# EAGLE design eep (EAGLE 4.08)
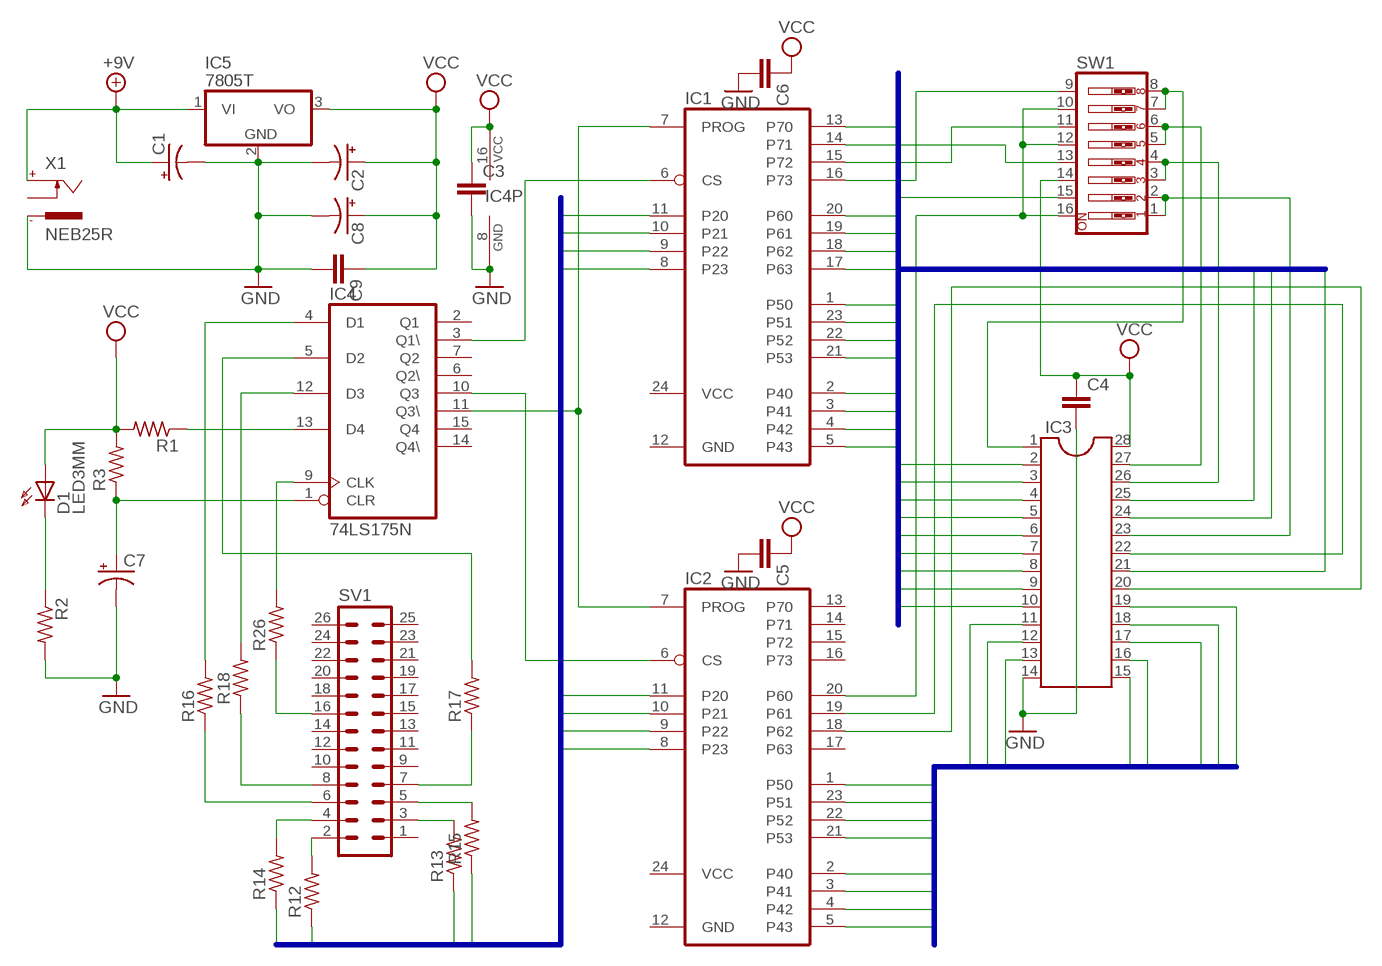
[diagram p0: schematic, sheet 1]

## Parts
C1  CPOL-USTAP5-80  [TAP5-80]
C2  CPOL-USTT2D5  [TT2D5]
C3  C5/2.5  [C5B2.5]
C4  C5/2.5  [C5B2.5]
C5  C5/2.5  [C5B2.5]
C6  C5/2.5  [C5B2.5]
C7  CPOL-USTAP5-50  [TAP5-50]
C8  CPOL-USTAP5-45  [TAP5-45]
C9  C5/2.5  [C5B2.5]
D1  LED3MM  [LED3MM]
IC1  IOEX-8243  [DIL24-6]
IC2  IOEX-8243  [DIL24-6]
IC3  DIL28  [DIL28-6]
IC4  74LS175N  [DIL16]
IC5  7805T  [TO220H]
R1  R-US_0207/10  [0207/10]
R2  R-US_0207/10  [0207/10]
R3  R-US_0207/10  [0207/10]
R12  R-US_0207/10  [0207/10]
R13  R-US_0207/10  [0207/10]
R14  R-US_0207/10  [0207/10]
R15  R-US_0207/10  [0207/10]
R16  R-US_0207/10  [0207/10]
R17  R-US_0207/10  [0207/10]
R18  R-US_0207/10  [0207/10]
R26  R-US_0207/10  [0207/10]
SV1  MA13-2  [MA13-2]
SW1  SW_DIP-8  [EDG-08]
X1  NEB25R  [NEB25R]

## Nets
+9V: C1.+ IC5.1(VI) X1.+
A11WE: IC3.23 SW1.1 SW1.2
A13VCC: IC3.26 SW1.3 SW1.4
A14WE: IC3.27 SW1.5 SW1.6
A15WE: IC3.1 SW1.7 SW1.8
AB0: IC1.2(P40) IC3.10
AB1: IC1.3(P41) IC3.9
AB2: IC1.4(P42) IC3.8
AB3: IC1.5(P43) IC3.7
AB4: IC1.1(P50) IC3.6
AB5: IC1.23(P51) IC3.5
AB6: IC1.22(P52) IC3.4
AB7: IC1.21(P53) IC3.3
AB8: IC1.20(P60) IC3.25
AB9: IC1.19(P61) IC3.24
AB10: IC1.18(P62) IC3.21
AB11: IC1.17(P63) SW1.15
AB12: IC1.13(P70) IC3.2
AB13: IC1.14(P71) SW1.13
AB14: IC1.15(P72) SW1.11
AB15: IC1.16(P73) SW1.9
CE: IC2.18(P62) IC3.20
CLK: IC4.9(CLK) R26.2
CLR: C7.+ IC4.1(CLR) R3.1
CS1: IC1.6(CS) IC4.3(Q1\)
CS2: IC2.6(CS) IC4.10(Q3)
D1: IC4.4(D1) R16.2
D2: IC4.5(D2) R17.2
D3: IC4.12(D3) R18.2
D4: IC4.13(D4) R1.1
DB0: IC2.2(P40) IC3.11
DB1: IC2.3(P41) IC3.12
DB2: IC2.4(P42) IC3.13
DB3: IC2.5(P43) IC3.15
DB4: IC2.1(P50) IC3.16
DB5: IC2.23(P51) IC3.17
DB6: IC2.22(P52) IC3.18
DB7: IC2.21(P53) IC3.19
GND [power]: C1.- C2.- C3.2 C4.2 C5.2 C6.2 C7.- C8.- C9.2 IC3.14 IC4.8(GND) IC5.2(GND) R2.2 X1.-
N$20: D1.K(C) R2.1
NC2: R12.2 SV1.2
NC3: R13.2 SV1.3
NC4: R14.2 SV1.4
NC5: R15.2 SV1.5
NC6: R16.1 SV1.6
NC7: R17.1 SV1.7
NC8: R18.1 SV1.8
NC16: R26.1 SV1.16
OE: IC2.19(P61) IC3.22
PROG: IC1.7(PROG) IC2.7(PROG) IC4.11(Q3\)
PROG0: IC1.11(P20) IC2.11(P20) R12.1
PROG1: IC1.10(P21) IC2.10(P21) R13.1
PROG2: IC1.9(P22) IC2.9(P22) R14.1
PROG3: IC1.8(P23) IC2.8(P23) R15.1
VCC [power]: C2.+ C3.1 C4.1 C5.1 C6.1 C8.+ C9.1 D1.A IC3.28 IC4.16(VCC) IC5.3(VO) R1.2 R3.2 SW1.14
WE: IC2.20(P60) SW1.10 SW1.12 SW1.16
Unconnected: IC2.13(P70) IC2.14(P71) IC2.15(P72) IC2.16(P73) IC2.17(P63) IC4.2(Q1) IC4.6(Q2\) IC4.7(Q2) IC4.14(Q4\) IC4.15(Q4) SV1.1 SV1.9 SV1.10 SV1.11 SV1.12 SV1.13 SV1.14 SV1.15 SV1.17 SV1.18 SV1.19 SV1.20 SV1.21 SV1.22 SV1.23 SV1.24 SV1.25 SV1.26 X1.C

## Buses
PROG[0..3]
DB[0..7]
AB[0..15]

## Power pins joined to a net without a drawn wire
GND: IC1.12(GND) IC2.12(GND)
VCC: IC1.24(VCC) IC2.24(VCC)

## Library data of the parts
C1 C2 C7 C8 = rcl:CPOL-US: POLARIZED CAPACITOR, American symbol
C3-C6 C9 = capacitor-wima:C: CAPACITOR
D1 = led:LED3MM: LED
IC1 IC2 = micro-intel:IOEX-8243: MICROCOMPUTER/PERIPHERAL DEVICE
IC3 = dil:DIL28: SOCKET Dual In Line
IC4 = 74xx-us:74*175: Qadruple D type FLIP FLOP, clear
IC5 = linear:78*: Positive VOLTAGE REGULATOR
R1-R3 R12-R18 R26 = rcl:R-US_: RESISTOR, American symbol
SV1 = con-lstb:MA13-2: PIN HEADER
SW1 = special:SW_DIP-8: DIP SWITCH
X1 = con-lumberg:NEB25R: CONNECTOR

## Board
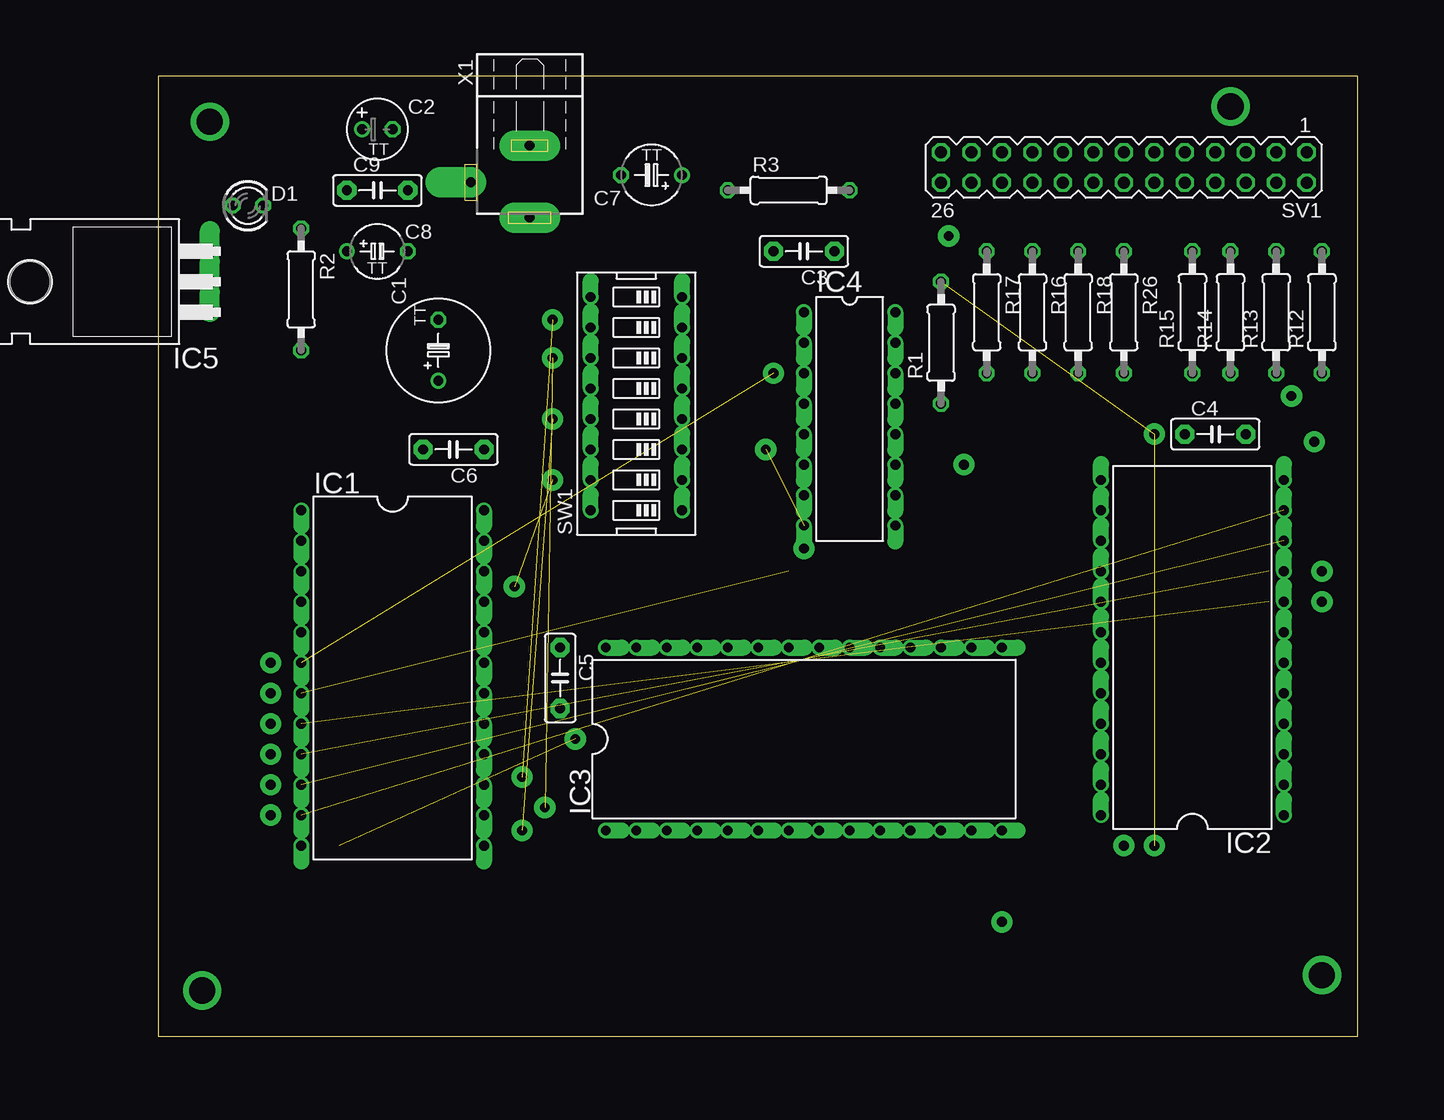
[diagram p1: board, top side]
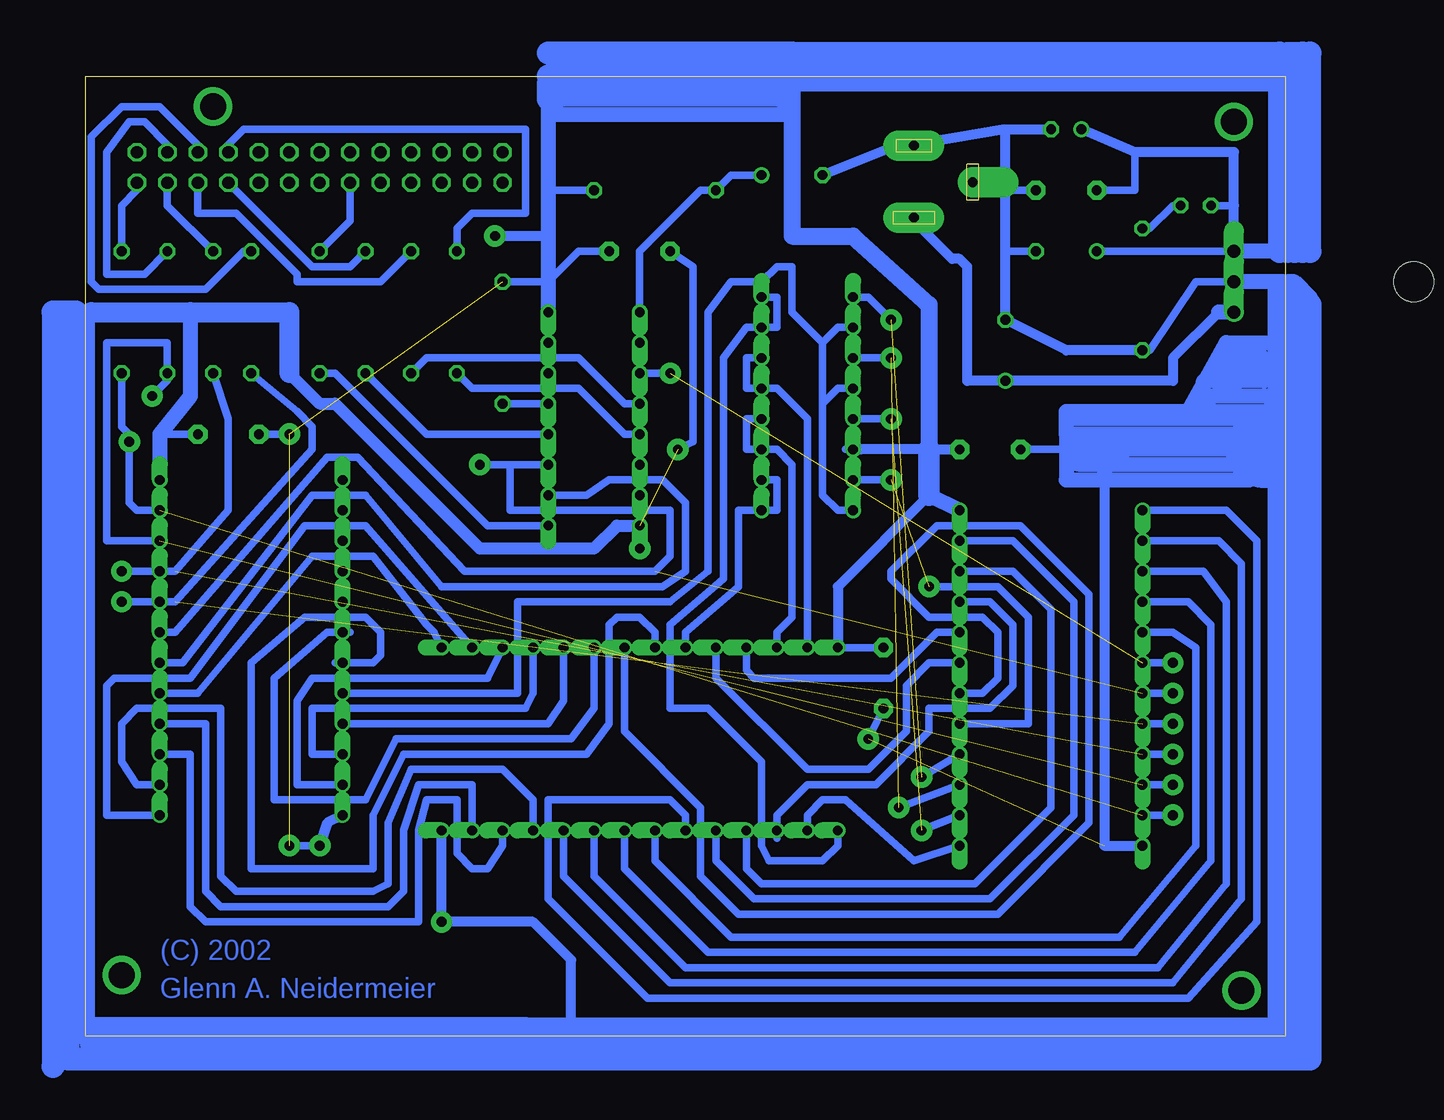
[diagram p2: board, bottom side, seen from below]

Size 100 x 80 mm. Coordinates in mm from the lower left corner, seen from the top.
Outline: 0,0 100,0 100,80 0,80 0,0
Copper layers used: Bottom

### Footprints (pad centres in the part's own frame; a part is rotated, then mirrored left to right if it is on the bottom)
TAP5-80 = drill 0.813 round: + -2.54,0 | drill 0.813 octagon: - 2.54,0
TT2D5 = drill 0.813 round: + -1.27,0 | drill 0.813 octagon: - 1.27,0
C5B2.5 = drill 0.813 pad 1.6 octagon: 1 -2.54,0; 2 2.54,0
TAP5-50 = drill 0.813 round: + -2.54,0 | drill 0.813 octagon: - 2.54,0
TAP5-45 = drill 0.813 round: + -2.54,0 | drill 0.813 octagon: - 2.54,0
LED3MM = drill 0.813 octagon: A -1.27,0; K 1.27,0
DIL24-6 = drill 0.813 offset: 1 -13.97,-7.62; 2 -11.43,-7.62; 3 -8.89,-7.62; 4 -6.35,-7.62; 5 -3.81,-7.62; 6 -1.27,-7.62; 7 1.27,-7.62; 8 3.81,-7.62; 9 6.35,-7.62; 10 8.89,-7.62; 11 11.43,-7.62; 12 13.97,-7.62; 13 13.97,7.62; 14 11.43,7.62; 15 8.89,7.62; 16 6.35,7.62; 17 3.81,7.62; 18 1.27,7.62; 19 -1.27,7.62; 20 -3.81,7.62; 21 -6.35,7.62; 22 -8.89,7.62; 23 -11.43,7.62; 24 -13.97,7.62
DIL28-6 = drill 0.813 offset: 1 -16.51,-7.62; 2 -13.97,-7.62; 3 -11.43,-7.62; 4 -8.89,-7.62; 5 -6.35,-7.62; 6 -3.81,-7.62; 7 -1.27,-7.62; 8 1.27,-7.62; 9 3.81,-7.62; 10 6.35,-7.62; 11 8.89,-7.62; 12 11.43,-7.62; 13 13.97,-7.62; 14 16.51,-7.62; 15 16.51,7.62; 16 13.97,7.62; 17 11.43,7.62; 18 8.89,7.62; 19 6.35,7.62; 20 3.81,7.62; 21 1.27,7.62; 22 -1.27,7.62; 23 -3.81,7.62; 24 -6.35,7.62; 25 -8.89,7.62; 26 -11.43,7.62; 27 -13.97,7.62; 28 -16.51,7.62
DIL16 = drill 0.813 offset: 1 -8.89,-3.81; 2 -6.35,-3.81; 3 -3.81,-3.81; 4 -1.27,-3.81; 5 1.27,-3.81; 6 3.81,-3.81; 7 6.35,-3.81; 8 8.89,-3.81; 9 8.89,3.81; 10 6.35,3.81; 11 3.81,3.81; 12 1.27,3.81; 13 -1.27,3.81; 14 -3.81,3.81; 15 -6.35,3.81; 16 -8.89,3.81
TO220H = drill 1.118 offset: 1 -2.54,-10.16; 2 0,-10.16; 3 2.54,-10.16 | hole 3.302: 0,4.826
0207/10 = drill 0.813 octagon: 1 -5.08,0; 2 5.08,0
MA13-2 = drill 1.016 octagon: 1 -15.24,-1.27; 2 -15.24,1.27; 3 -12.7,-1.27; 4 -12.7,1.27; 5 -10.16,-1.27; 6 -10.16,1.27; 7 -7.62,-1.27; 8 -7.62,1.27; 9 -5.08,-1.27; 10 -5.08,1.27; 11 -2.54,-1.27; 12 -2.54,1.27; 13 0,-1.27; 14 0,1.27; 15 2.54,-1.27; 16 2.54,1.27; 17 5.08,-1.27; 18 5.08,1.27; 19 7.62,-1.27; 20 7.62,1.27; 21 10.16,-1.27; 22 10.16,1.27; 23 12.7,-1.27; 24 12.7,1.27; 25 15.24,-1.27; 26 15.24,1.27
EDG-08 = drill 0.813 offset: 1 -8.89,-3.81; 2 -6.35,-3.81; 3 -3.81,-3.81; 4 -1.27,-3.81; 5 1.27,-3.81; 6 3.81,-3.81; 7 6.35,-3.81; 8 8.89,-3.81; 9 8.89,3.81; 10 6.35,3.81; 11 3.81,3.81; 12 1.27,3.81; 13 -1.27,3.81; 14 -3.81,3.81; 15 -6.35,3.81; 16 -8.89,3.81
NEB25R = drill 0.813 pad 2.54 long: + 0,7.35; - 0,1.35 | drill 0.813 pad 2.54 offset: C 4.9,4.4

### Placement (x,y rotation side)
C1  23.33,57.15 90 top
C2  18.25,75.56 0 top
C3  53.81,65.4 180 top
C4  88.1,50.16 0 top
C5  33.49,29.84 270 top
C6  24.6,48.89 180 top
C7  41.11,71.75 180 top
C8  18.25,65.4 0 top
C9  18.25,70.48 0 top
D1  7.46,69.21 0 top
IC1  19.52,29.84 270 top
IC2  86.19,32.38 90 top
IC3  53.81,24.76 0 top
IC4  57.62,51.43 270 top
IC5  -5.88,62.86 90 top
R1  65.24,57.78 90 top
R2  11.9,62.23 270 top
R3  52.54,70.48 0 top
R12  96.99,60.32 90 top
R13  93.18,60.32 90 top
R14  89.37,60.32 90 top
R15  86.19,60.32 90 top
R16  72.86,60.32 270 top
R17  69.05,60.32 270 top
R18  76.67,60.32 270 top
R26  80.48,60.32 270 top
SV1  80.48,72.38 180 top
SW1  39.84,52.7 90 top
X1  30.95,75.56 180 top

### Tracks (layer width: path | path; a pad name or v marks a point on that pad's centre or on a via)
+9V
  Bottom 0.61: 30.95,67.94 X1.+
  Bottom 0.813: 30.95,67.94 27.77,64.77 27.14,64.77 26.5,64.13 26.5,54.61 C1.+ 9.36,54.61 9.36,56.51 5.55,60.32
  Bottom 1.27: IC5.1 5.55,60.32
A11WE
  Bottom 0.61: SW1.2 42.38,46.35 42.38,43.81 SW1.1 45.55,43.81 45.55,37.46 50,33.65 IC3.23
A13VCC
  Bottom 0.61: IC3.26 42.38,33.65 41.11,34.92 41.11,47.62 42.38,48.89 SW1.3 44.92,48.89 44.92,51.43 SW1.4
A14WE
  Bottom 0.61: IC3.27 39.84,51.43 42.38,53.97 SW1.5 44.92,53.97 44.92,56.51 SW1.6
A15WE
  Bottom 0.61: SW1.8 42.38,61.59 42.38,59.05 SW1.7 44.92,59.05 46.82,56.51 46.82,38.1 47.5,37.51 51.27,34.29 51.27,27.3 48.09,27.3 43.65,22.86 43.65,15.87 43.02,14.6 38.57,14.6 37.3,15.87 IC3.1
AB0
  Bottom 0.61: IC1.2 5.55,41.27 3.64,39.37 3.64,11.43 9.36,4.44 51.27,4.44 60.16,13.33 IC3.10
AB1
  Bottom 0.61: IC1.3 6.82,38.73 4.92,36.19 4.92,12.7 10.63,5.71 50,5.71 57.62,13.33 IC3.9
AB2
  Bottom 0.61: IC3.8 55.08,13.97 48.09,6.98 12.54,6.98 6.18,14.6 6.18,34.29 8.09,36.19 IC1.4
AB3
  Bottom 0.61: IC3.7 52.54,14.6 46.19,8.25 13.81,8.25 7.46,15.87 7.46,32.38 9.36,33.65 IC1.5
AB4
  Bottom 0.61: IC1.1 4.92,43.81 2.38,41.27 2.38,9.52 8.09,3.17 53.17,3.17 61.43,11.43 61.43,19.68 51.27,19.68 50,18.41 IC3.6
AB5
  Bottom 0.61: IC3.5 47.46,14.6 44.28,11.43 24.6,11.43 17.61,18.41 17.61,36.19 22.7,41.27 IC1.23
AB6
  Bottom 0.61: IC3.4 44.92,13.97 43.65,12.7 25.87,12.7 19.52,19.04 19.52,35.55 22.7,38.73 IC1.22
AB7
  Bottom 0.61: IC1.21 24.6,36.19 22.7,34.29 22.7,29.2 24.6,27.3 29.68,27.3 29.68,25.39 34.12,20.95 39.84,20.95 42.38,18.41 IC3.3 42.38,16.5
AB8
  Bottom 0.61: IC3.25 44.92,30.47 44.28,29.84 32.85,29.84 29.04,33.65 IC1.20
AB9
  Bottom 0.61: IC1.19 29.68,31.11 31.58,29.2 31.58,25.39 34.76,22.22 39.84,22.22 47.46,29.84 IC3.24
AB10
  Bottom 0.61: IC3.21 55.08,25.39 48.73,19.04 48.73,13.33 45.55,10.16 23.96,10.16 16.34,17.77 16.34,36.83 22.06,42.54 29.04,42.54 32.85,38.73 32.85,38.1 29.68,34.92 25.23,34.92 23.96,33.65 23.96,29.84 25.23,28.57 IC1.18
AB11  (via drill 0.81 pad 1.78)  (1 unrouted)
  Bottom 0.61: IC1.17 21.42,26.03 21.42,34.92 23.96,37.46 v29.68,37.46 | v32.85,46.35 SW1.15
AB12
  Bottom 0.61: IC1.13 30.95,14.6 36.66,19.68 38.57,19.68 39.84,18.41 IC3.2
AB13  (via drill 0.81 pad 1.78)  (1 unrouted)
  Bottom 0.61: IC1.14 v30.31,17.14 | v32.85,51.43 SW1.13
AB14  (via drill 0.81 pad 1.78)  (1 unrouted)
  Bottom 0.61: IC1.15 v32.22,19.04 | v32.85,56.51 SW1.11
AB15  (via drill 0.81 pad 1.78)  (1 unrouted)
  Bottom 0.61: IC1.16 v30.31,21.58 | SW1.9 34.76,61.59 v32.85,59.69
CE
  Bottom 0.61: IC3.20 57.62,27.3 59.52,24.76 74.13,24.76 76.67,19.68 84.29,19.68 84.29,29.84 79.84,33.65 IC2.18 77.94,33.65
CLK
  Bottom 0.61: IC4.9 66.51,42.54 79.21,55.24 R26.2
CLR
  Bottom 0.61: IC4.1 53.81,65.4 48.73,70.48 R3.1 46.19,71.75 C7.+
CS1  (via drill 0.81 pad 1.78)  (1 unrouted)
  Bottom 0.61: v9.36,31.11 IC1.6 | v51.27,55.24 IC4.3
CS2
  Bottom 0.61: IC4.10 58.25,45.08 56.35,46.35 51.91,46.35 50,44.45 50,38.73 51.91,37.46 70.32,37.46 76.67,45.08 81.11,45.08 91.91,31.11 IC2.6
D1
  Bottom 0.61: R16.2 71.59,56.51 58.89,56.51 55.08,52.7 IC4.4
D2
  Bottom 0.61: R17.2 67.78,53.97 58.89,53.97 55.08,50.16 IC4.5
D3
  Bottom 0.61: R18.2 71.59,50.16 IC4.12
D4
  Bottom 0.61: IC4.13 R1.1
DB0
  Bottom 0.61: IC3.11 62.7,19.68 65.24,22.22 72.86,22.22 74.77,17.77 74.77,12.7 76.03,12.06 87.47,12.06 88.73,13.33 88.73,27.3 95.72,27.3 96.99,26.03 96.99,22.86 95.72,20.95 IC2.2
DB1
  Bottom 0.61: IC2.3 91.28,23.49 91.28,10.79 90,9.52 72.22,9.52 72.22,17.14 71.59,19.68 69.05,19.68 69.05,15.24 67.78,13.97 66.51,13.97 65.24,15.87 IC3.12
DB2
  Bottom 0.61: IC3.13 67.78,20.95 72.22,20.95 73.5,17.14 73.5,12.06 74.77,10.79 88.73,10.79 90,12.06 90,26.03 IC2.4
DB3
  Bottom 0.61: IC3.15 70.95,33.65 71.59,34.29 76.03,40 81.11,40 90.64,28.57 IC2.5
DB4
  Bottom 0.61: IC3.16 76.67,42.54 81.75,42.54 91.28,29.84 97.62,29.84 98.26,29.2 98.26,18.41 IC2.1
DB5
  Bottom 0.61: IC3.17 66.51,29.84 81.11,29.84 82.39,27.93 82.39,20.95 IC2.23
DB6
  Bottom 0.61: IC3.18 62.7,28.57 63.34,27.3 81.11,27.3 81.11,23.49 IC2.22
DB7
  Bottom 0.61: IC3.19 60.16,27.93 61.43,26.03 IC2.21
GND  (via drill 0.81 pad 1.78)  (2 unrouted)
  Bottom 0.61: 16.98,48.89 C6.2 | v34.76,24.76 C5.2 | 99.53,0.63 99.53,60.32 | R2.2 11.27,57.15 7.46,62.86 IC5.2 | 23.33,70.48 C9.2 | 23.33,65.4 C8.- | 29.71,74.5 29.68,74.29 X1.- 32.22,74.29 | IC4.8 v53.81,40.64 | 93.81,50.16 C4.2 | v50.63,48.89 49.37,49.53 49.37,64.13 C3.2
  Bottom 0.813: IC3.14 v70.32,9.52 62.7,9.52 59.52,6.34 59.52,1.27 60.16,0.63 63.34,0.63 | 15.08,47.62 15.08,48.89 | 15.08,46.35 15.08,15.87 IC1.12 | IC4.8 55.08,42.54 | R2.2 18.25,57.15 C1.- 23.33,65.4 23.33,70.48 23.33,75.56 | 23.33,75.56 C2.- | 23.33,75.56 29.71,74.5 30.95,74.29 | 32.22,74.29 C7.-
  Bottom 1.016: 83.02,55.24 80.48,52.7 79.21,52.7 67.14,40.64 57.62,40.64 55.71,42.54 IC4.8
  Bottom 1.27: 1.74,48.89 2.38,48.89 | 2.38,48.89 2.38,50.16 | 2.38,50.16 13.17,50.16 13.17,48.89 3.64,48.89 | 2.38,48.89 3.64,48.89 | 3.64,48.89 3.64,47.62 15.08,47.62 15.08,46.35 | 15.08,46.35 3.01,46.35 | 15.08,46.35 18.25,46.35 18.25,50.16 | 18.25,50.16 18.25,51.43 2.38,51.43 2.38,50.16 | 2.38,50.16 18.25,50.16 | 18.25,50.16 18.25,52.07 8.09,52.07 | 8.09,52.07 1.1,52.07 1.1,53.34 6.82,53.34 6.82,54.61 1.74,54.61 1.74,55.88 | 1.74,55.88 1.74,56.51 5.55,56.51 5.55,55.24 1.74,55.88 | 8.09,52.07 1.74,55.88 | 8.09,52.07 4.92,57.78 1.1,57.78 | 91.28,60.32 91.28,53.34 93.81,50.16 IC2.12 | -0.8,62.86 IC5.2 | -0.8,62.86 -2.07,61.59 | -0.8,62.23 -0.8,62.86
  Bottom 1.676: 0.47,48.89 0.47,62.23 -0.17,62.23 | 99.53,60.32 91.28,60.32 83.02,60.32 83.02,55.24
  Bottom 1.93: 0.47,62.23 0.47,0.63 63.34,0.63 | 63.34,0.63 99.53,0.63 99.53,-0.64 -0.8,-0.64 | -0.8,-0.64 -1.44,-0.64 -1.44,61.59 | -2.07,60.96 -2.07,-1.91 101.44,-1.91 100.8,60.32 102.7,60.32 102.7,-2.54 100.8,1.27 100.8,58.41 | -0.8,-0.64 63.34,0.63 | -0.8,-0.64 -0.8,62.23 -1.44,61.59 | -1.44,61.59 -2.07,60.96 | -2.07,60.96 -0.17,62.23
  Bottom 3.81: 15.08,48.89 16.98,48.89
  Bottom 6.452: 0.47,48.89 1.74,48.89
N$2  (via drill 2.18)
  other vias: 4.28,76.19
N$3  (via drill 2.18)
  other vias: 89.37,77.46
N$4  (via drill 2.18)
  other vias: 96.99,5.08
N$5  (via drill 2.18)
  other vias: 3.64,3.8
N$20
  Bottom 0.61: D1.K 9.36,69.21 11.27,67.3 R2.1
NC2
  Bottom 0.61: R12.2 96.99,69.21 95.72,70.48 SV1.2
NC3
  Bottom 0.61: R13.2 95.08,63.5 98.26,63.5 98.26,73.66 96.36,76.19 95.08,76.19 93.18,74.29 SV1.3
NC4
  Bottom 0.61: R14.2 93.18,69.21 SV1.4
NC5
  Bottom 0.61: SV1.5 90.64,74.29 93.81,77.46 96.99,77.46 99.53,74.92 99.53,62.86 98.89,62.23 90,62.23 86.83,65.4 R15.2
NC6
  Bottom 0.61: R16.1 75.4,62.86 82.39,62.86 82.39,63.5 87.47,68.57 90.64,68.57 SV1.6
NC7
  Bottom 0.61: SV1.7 88.1,74.29 86.83,75.56 63.34,75.56 63.34,68.57 67.78,68.57 69.05,67.3 R17.1
NC8
  Bottom 0.61: R18.1 77.94,64.13 81.11,64.13 SV1.8
NC16
  Bottom 0.61: R26.1 77.94,67.94 SV1.16
OE
  Bottom 0.61: IC3.22 52.54,33.65 53.81,34.92 55.71,34.92 56.35,34.29 56.35,26.03 58.25,23.49 73.5,23.49 76.03,18.41 76.03,13.97 86.19,13.97 86.19,31.11 81.75,34.92 76.67,34.92 75.4,33.65 75.4,31.74 76.03,31.11 IC2.19 79.21,31.11
PROG  (via drill 0.81 pad 1.78)  (1 unrouted)
  Bottom 0.61: v9.36,28.57 IC1.7 | IC2.7 92.55,33.65 79.84,48.26 77.3,48.26 68.41,38.73 52.54,38.73 51.27,40 51.27,43.81 64.61,43.81 64.61,47.62 | 64.61,47.62 IC4.11 | 64.61,47.62 v67.14,47.62
PROG0  (via drill 0.81 pad 1.78)  (1 unrouted)
  Bottom 0.61: v9.36,18.41 IC1.11 | IC2.11 95.72,43.81 96.36,44.45 v96.36,49.53 96.36,50.16 96.99,50.8 R12.1
PROG1  (via drill 0.81 pad 1.78)  (1 unrouted)
  Bottom 0.61: v9.36,20.95 IC1.10 | IC2.10 98.26,41.27 98.26,57.78 93.18,57.78 R13.1 93.18,54.61 v94.45,53.34
PROG2  (via drill 0.81 pad 1.78)  (1 unrouted)
  Bottom 0.61: v9.36,23.49 IC1.9 | R14.1 88.1,51.43 88.1,43.81 92.55,38.73 IC2.9 | IC2.9 v96.99,38.73 IC2.9
PROG3  (via drill 0.81 pad 1.78)  (1 unrouted)
  Bottom 0.61: v9.36,26.03 IC1.8 | R15.1 82.39,52.07 81.11,50.8 81.11,48.89 92.55,36.19 IC2.8 v96.99,36.19
VCC  (via drill 0.81 pad 1.78)  (2 unrouted)
  Bottom 0.61: IC3.28 C5.1 | v80.48,15.87 v83.02,15.87 | v83.02,50.16 C4.1 | C3.1 58.89,65.4 61.43,62.86 R1.2 | IC5.3 C8.+ | C9.1 12.54,70.48 12.54,73.66 | 61.43,70.48 R3.2 | 4.28,69.21 D1.A | 35.39,48.89 SW1.14 36.66,48.89
  Bottom 0.813: IC3.28 37.3,37.46 29.68,45.08 | C6.1 29.68,48.89 35.39,48.89 | IC5.3 4.28,69.21 4.28,73.66 12.54,73.66 C2.+ | 61.43,66.67 v65.88,66.67 | IC2.24 79.84,17.77 v80.48,15.87 | 61.43,80 61.43,79.37
  Bottom 1.27: 29.68,45.08 IC1.24 | 61.43,79.37 41.11,79.37 41.11,78.73 41.11,67.94 | IC4.16 61.43,62.86 61.43,66.67 61.43,70.48 61.43,78.1 60.8,76.83 | 61.43,79.37 1.1,79.37 | 61.43,79.37 60.16,78.1 41.74,78.1 41.74,76.83 60.8,76.83 | 60.8,76.83 60.8,81.91 | 0.47,65.4 IC5.3
  Bottom 1.422: 29.68,48.89 29.68,60.96 36.03,66.67 41.11,66.67 41.11,78.73
  Bottom 1.778: 29.68,48.89 29.68,45.08
  Bottom 1.93: 0.47,65.4 0.47,80 61.43,80 -1.44,81.91 -1.44,65.4 -2.07,65.4 -2.07,81.91 -0.17,80 -0.8,65.4 -0.17,65.4 | 41.11,79.37 41.11,81.91 | 41.11,81.91 0.47,81.91 | 41.11,81.91 60.8,81.91 61.43,81.91 | 61.43,79.37 61.43,78.1
WE
  Bottom 0.61: 38.57,52.7 38.57,45.08 37.3,43.81 SW1.16 | 38.57,52.7 37.3,53.97 SW1.12 | 38.57,52.7 38.57,57.78 | IC2.20 63.97,28.57 63.97,36.19 51.27,36.19 48.09,38.73 48.09,60.32 46.19,62.86 43.65,62.86 42.38,64.13 41.11,64.13 41.11,60.32 38.57,57.78 | 38.57,57.78 37.3,59.05 SW1.10

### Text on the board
Bottom: (C) 2002 | Glenn A. Neidermeier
